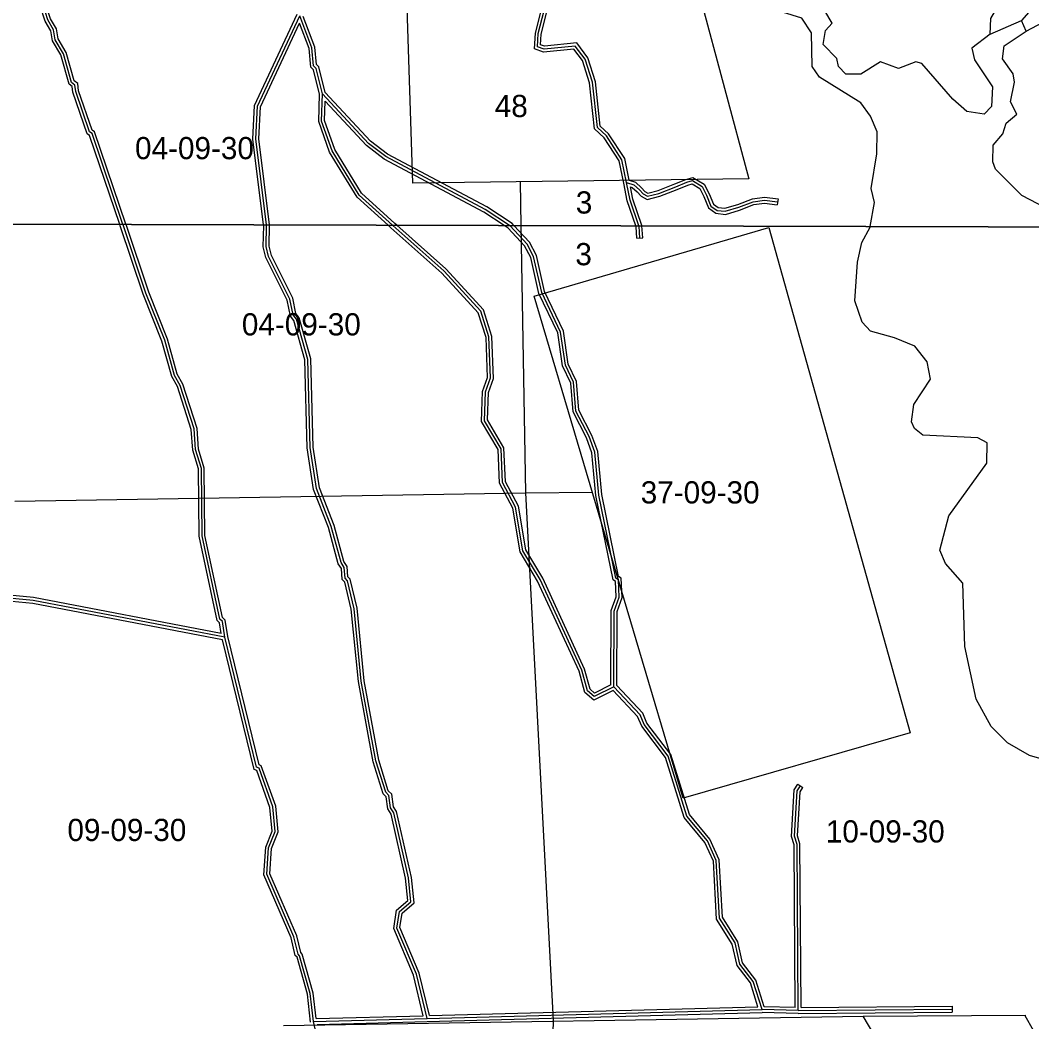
# Model space of a CAD drawing. Extents: x 418523 to 616617, y 1878279 to 2196743.
# Drawn here: x 563379 to 573626, y 1961144 to 1971295 of the extents above; entities that cross this region are included whole.
import ezdxf

# ---------------------------------------------------------------- set-up
doc = ezdxf.new("R2010")
doc.units = 0
for name, color, linetype in [('Level 1', 7, 'Continuous'), ('Level 2', 7, 'Continuous'), ('Level 31', 7, 'Continuous'), ('Level 32', 7, 'Continuous'), ('Level 5', 7, 'Continuous'), ('Level 63', 7, 'Continuous'), ('Level 7', 7, 'Continuous')]:
    doc.layers.add(name, color=color, linetype=linetype)

msp = doc.modelspace()

# ---------------------------------------------------------------- linework, layer by layer
at = {"layer": 'Level 1'}
for p, q in [((567356.046, 1969642.211), (567262.093, 1972599.901)), ((570215.137, 1971717.725), (570759.854, 1969688.182)), ((570759.854, 1969688.182), (567356.046, 1969642.211)), ((568442.603, 1969656.886), (568450.437, 1969213.046)), ((568450.439, 1969213.046), (568498.229, 1966505.171)), ((568584.936, 1968498.066), (570961.931, 1969193.848)), ((570961.931, 1969193.848), (572392.411, 1964072.356)), ((570093.531, 1963410.441), (568584.936, 1968498.066)), ((563325.605, 1966421.114), (568498.229, 1966505.171)), ((568498.229, 1966505.171), (569174.423, 1966510.066)), ((568498.229, 1966505.171), (568776.511, 1961155.102)), ((572392.411, 1964072.356), (570093.531, 1963410.441)), ((566044.955, 1961105.029), (571916.201, 1961201.744)), ((571916.201, 1961201.744), (573565.651, 1961210.564)), ((573305.676, 1958862.184), (571916.201, 1961201.744)), ((573555.637, 1961206.581), (574887.717, 1958874.766)), ((568776.511, 1961155.102), (568644.303, 1955869.218))]:
    msp.add_line(p, q, dxfattribs=at)
at = {"layer": 'Level 31'}
for p, q in [((567499.95, 1961176.461), (570893, 1961267.367)), ((571259.908, 1961257.792), (570893, 1961267.367)), ((571259.908, 1961257.792), (572818.751, 1961270.236)), ((566349.567, 1961146.156), (567499.95, 1961176.461))]:
    msp.add_line(p, q, dxfattribs=at)
for points in [[(569521.172, 1969648.749), (569474.434, 1969880.869), (569316.651, 1970123.071), (569225.138, 1970206.562), (569176.398, 1970665.243), (569101.742, 1970898.885), (569002.099, 1971032.581), (568685.327, 1970999.876), (568618.747, 1971025.127), (568627.315, 1971158.567), (568686.256, 1971391.892), (568753.449, 1971491.737), (568737.065, 1971675.057)], [(564418.857, 1969223.903), (564106.349, 1970145.186), (564081.32, 1970161.976), (563940.811, 1970571.075), (563932.728, 1970637.644), (563899.47, 1970662.819), (563816.744, 1970954.676), (563733.641, 1971096.71), (563717.392, 1971196.756), (563659.254, 1971296.906), (563609.811, 1971447.22), (563601.704, 1971630.521)], [(565874.59, 1969219.983), (565765.254, 1970090.891), (565782.573, 1970424.318), (566210.352, 1971340.039)], [(566441.659, 1970547.438), (566375.649, 1970806.156), (566350.64, 1970831.31), (566334.586, 1971014.63), (566210.352, 1971340.039)], [(567150.249, 1969216.548), (566813.943, 1969521.031), (566540.22, 1969971.899), (566432.422, 1970272.539), (566441.659, 1970547.438)], [(568336.904, 1969213.352), (568088.994, 1969375.771), (567081.772, 1969912.037), (566907.242, 1970045.92), (566441.659, 1970547.438)], [(569521.172, 1969648.749), (569594.74, 1969625.301), (569650.474, 1969575.351), (569688.459, 1969534.532), (569732.198, 1969510.791), (569849.365, 1969539.973), (570021.839, 1969607.572), (570130.155, 1969651.685), (570188.587, 1969669.003), (570285.239, 1969610.23), (570332, 1969522.116), (570375.852, 1969410.737), (570437.314, 1969366.592), (570519.168, 1969357.674), (570656.673, 1969398.811), (570803.096, 1969454.473), (570917.063, 1969472.028), (571051.575, 1969454.261)], [(569646.29, 1969209.826), (569556.616, 1969471.931), (569521.172, 1969648.749)], [(565451.352, 1965041.616), (565426.669, 1965199.866), (565401.657, 1965225.02), (565220.61, 1966067.686), (565214.046, 1966751.005), (565156.126, 1966943.157), (565140.137, 1967151.569), (564999.688, 1967593.756), (564941.542, 1967693.903), (564842.464, 1968052.711), (564651.963, 1968528.478), (564420.431, 1969219.268), (564418.859, 1969223.903)], [(567499.95, 1961176.461), (567392.797, 1961626.921), (567193.956, 1962093.966), (567219.435, 1962260.82), (567336.479, 1962360.542), (567311.987, 1962602.43), (567163.766, 1963261.361), (567130.56, 1963311.261), (567114.357, 1963436.397), (567081.112, 1963469.933), (566981.9, 1963786.914), (566834.053, 1964596.035), (566760.931, 1965329.7), (566694.971, 1965613.509), (566669.959, 1965638.661), (566661.971, 1965747.049), (566628.767, 1965796.951), (566529.688, 1966164.116), (566380.506, 1966547.77), (566315.194, 1966965.039), (566292.3, 1967857.135), (566176.829, 1968265.799), (566143.609, 1968307.7), (566110.673, 1968465.97), (565894.986, 1968899.972), (565870.479, 1969000.037), (565875.133, 1969215.672), (565874.592, 1969219.983)], [(569392.991, 1964539.007), (569192.804, 1964439.476), (569126.292, 1964498.18), (569068.386, 1964706.689), (568645.59, 1965624.823), (568471.412, 1965917.25), (568397.566, 1966359.262), (568264.867, 1966609.408), (568249.18, 1966951.28), (568083.243, 1967235.325), (568092.191, 1967526.953), (568142.673, 1967668.657), (568127.167, 1968085.44), (568044.321, 1968344.195), (567670.196, 1968753.475), (567154.661, 1969212.556), (567150.251, 1969216.548)], [(569392.991, 1964539.007), (569395.116, 1965305.945), (569445.595, 1965447.65), (569437.755, 1965622.585), (569412.721, 1965639.371), (569239.836, 1966481.999), (569199.285, 1966915.567), (569141.264, 1967073.894), (569008.583, 1967332.764), (568984.521, 1967624.834), (568901.471, 1967799.948), (568852.436, 1968133.533), (568661.707, 1968534.368), (568579.433, 1968901.126), (568513.088, 1969026.38), (568342.476, 1969209.704), (568336.906, 1969213.352)], [(569655.359, 1969086.59), (569647.391, 1969206.615), (569646.292, 1969209.826)], [(565451.352, 1965041.616), (563509.914, 1965413.739), (562518.03, 1965507.888), (561585.104, 1965819.014), (560593.401, 1965855.031)], [(566349.567, 1961146.156), (566316.929, 1961429.52), (566209.629, 1961813.435), (566192.847, 1961830.203), (566151.694, 1962005.22), (565878.373, 1962639.371), (565895.531, 1962906.25), (565962.91, 1963072.637), (565938.449, 1963322.89), (565797.852, 1963715.251), (565772.799, 1963723.676), (565451.352, 1965041.616)], [(570893, 1961267.367), (570802.241, 1961550.861), (570669.337, 1961726.45), (570619.69, 1961943.302), (570462.203, 1962193.86), (570430.233, 1962777.231), (570339.289, 1962977.816), (570131.343, 1963228.492), (569941.377, 1963837.326), (569700.588, 1964154.995), (569658.929, 1964255.097), (569392.991, 1964539.007)], [(571259.908, 1961257.792), (571247.601, 1962941.891), (571223.036, 1963025.224), (571249.166, 1963483.729), (571282.607, 1963533.836)], [(566568.709, 1958977.895), (566419.856, 1959378.637), (566437.612, 1959761.882), (566471.368, 1959937.081), (566456.648, 1960670.601), (566349.567, 1961146.156)]]:
    msp.add_lwpolyline(points, dxfattribs=at)
at = {"layer": 'Level 32'}
for p, q in [((571055.504, 1969484.004), (571047.647, 1969424.519)), ((569685.294, 1969088.577), (569677.25, 1969209.742)), ((569625.424, 1969084.603), (569685.294, 1969088.577)), ((571257.654, 1963550.49), (571307.561, 1963517.181)), ((567523.501, 1961207.104), (570852.242, 1961296.286)), ((571229.681, 1961288.591), (570915.078, 1961296.801)), ((571289.69, 1961288.031), (572818.513, 1961300.235)), ((572818.513, 1961300.235), (572818.991, 1961240.236)), ((566376.23, 1961176.868), (567462.211, 1961205.478)), ((567500.754, 1961146.471), (570893.011, 1961237.355)), ((571259.637, 1961227.787), (570893.011, 1961237.356)), ((571259.636, 1961227.788), (572818.991, 1961240.236)), ((566386.856, 1961117.126), (567500.741, 1961146.471))]:
    msp.add_line(p, q, dxfattribs=at)
for points in [[(564387.149, 1969223.989), (564081.201, 1970125.931), (564056.225, 1970142.686), (563911.411, 1970564.32), (563904.479, 1970621.401), (563873.349, 1970644.966), (563788.921, 1970942.821), (563704.925, 1971086.383), (563688.666, 1971186.481), (563631.734, 1971284.556), (563580.022, 1971441.768), (563573.461, 1971590.122)], [(564450.545, 1969223.818), (564448.858, 1969228.854), (564131.497, 1970164.442), (564106.415, 1970181.267), (563970.212, 1970577.83), (563960.976, 1970653.887), (563925.593, 1970680.671), (563844.565, 1970966.531), (563762.358, 1971107.036), (563746.117, 1971207.029), (563686.774, 1971309.256), (563639.6, 1971452.671), (563633.47, 1971591.27)], [(569491.761, 1969642.826), (569446.158, 1969869.311), (569293.604, 1970103.488), (569196.509, 1970192.072), (569146.889, 1970659.028), (569074.691, 1970884.978), (568988.229, 1971000.988), (568681.335, 1970969.304), (568587.389, 1971004.935), (568597.553, 1971163.241), (568658.449, 1971404.306), (568722.62, 1971499.662), (568710.539, 1971634.848)], [(569547.099, 1969671.972), (569502.709, 1969892.427), (569339.699, 1970142.652), (569253.768, 1970221.052), (569205.907, 1970671.458), (569128.793, 1970912.792), (569015.969, 1971064.173), (568689.318, 1971030.449), (568650.106, 1971045.32), (568657.078, 1971153.892), (568714.064, 1971379.478), (568784.277, 1971483.812), (568770.348, 1971639.691)], [(565844.343, 1969220.064), (565735.155, 1970089.792), (565752.916, 1970431.716), (566185.139, 1971356.949)], [(565904.837, 1969219.901), (565795.352, 1970091.99), (565812.229, 1970416.92), (566207.574, 1971263.206)], [(566411.532, 1970544.167), (566348.603, 1970790.809), (566321.703, 1970817.865), (566305.064, 1971007.841), (566207.574, 1971263.206)], [(566468.84, 1970562.253), (566402.695, 1970821.504), (566379.579, 1970844.755), (566364.108, 1971021.418), (566245.009, 1971333.375)], [(567105.418, 1969216.669), (566790.566, 1969501.726), (566513.004, 1969958.921), (566402.245, 1970267.813), (566411.532, 1970544.167)], [(568380.169, 1969213.236), (568361.957, 1969232.806), (568104.295, 1969401.611), (567098.062, 1969937.352), (566927.508, 1970068.184), (566468.84, 1970562.252)], [(567195.424, 1969216.426), (567174.702, 1969234.878), (566837.319, 1969540.337), (566567.438, 1969984.877), (566462.598, 1970277.265), (566469.199, 1970473.677)], [(568281.934, 1969213.501), (568073.693, 1969349.93), (567065.482, 1969886.722), (566886.976, 1970023.656), (566469.199, 1970473.677)], [(569547.099, 1969671.972), (569609.975, 1969651.933), (569671.51, 1969596.784), (569707.081, 1969558.56), (569736.261, 1969542.721), (569840.228, 1969568.615), (570010.707, 1969635.431), (570120.21, 1969680.027), (570192.811, 1969701.546), (570307.873, 1969631.578), (570359.294, 1969534.684), (570400.529, 1969429.95), (570448.407, 1969395.562), (570516.384, 1969388.156), (570647.03, 1969427.241), (570795.397, 1969483.642), (570916.736, 1969502.332), (571055.504, 1969484.004)], [(569614.553, 1969209.911), (569527.589, 1969464.092), (569491.756, 1969642.852)], [(569677.248, 1969209.742), (569677.06, 1969212.566), (569585.642, 1969479.768), (569560.6, 1969604.694)], [(569560.601, 1969604.694), (569579.504, 1969598.67), (569629.439, 1969553.917), (569669.838, 1969510.505), (569728.134, 1969478.862), (569858.503, 1969511.331), (570032.972, 1969579.712), (570140.1, 1969623.341), (570184.362, 1969636.46), (570262.604, 1969588.881), (570304.705, 1969509.55), (570351.174, 1969391.525), (570426.221, 1969337.622), (570521.952, 1969327.192), (570666.315, 1969370.381), (570810.795, 1969425.305), (570917.389, 1969441.725), (571047.647, 1969424.519)], [(565415.142, 1965079.103), (565398.527, 1965185.62), (565374.176, 1965210.11), (565190.64, 1966064.356), (565184.088, 1966746.441), (565126.461, 1966937.616), (565110.491, 1967145.805), (564972.091, 1967581.537), (564913.654, 1967682.187), (564813.991, 1968043.112), (564623.792, 1968518.127), (564392.003, 1969209.683), (564387.151, 1969223.989)], [(565480.8, 1965047.491), (565454.81, 1965214.112), (565429.14, 1965239.93), (565250.58, 1966071.014), (565244.004, 1966755.569), (565185.789, 1966948.698), (565169.783, 1967157.334), (565027.286, 1967605.973), (564969.43, 1967705.62), (564870.937, 1968062.309), (564680.135, 1968538.83), (564450.547, 1969223.818)], [(567462.211, 1961205.478), (567364.199, 1961617.506), (567163.011, 1962090.061), (567191.465, 1962276.403), (567305.046, 1962373.174), (567282.322, 1962597.609), (567135.715, 1963249.362), (567101.706, 1963300.468), (567085.907, 1963422.482), (567054.663, 1963454), (566952.719, 1963779.711), (566804.321, 1964591.844), (566731.271, 1965324.796), (566667.68, 1965598.406), (566640.856, 1965625.381), (566632.63, 1965736.988), (566601.078, 1965784.407), (566501.143, 1966154.745), (566351.369, 1966539.923), (566285.254, 1966962.323), (566262.406, 1967852.601), (566149.591, 1968251.865), (566115.685, 1968294.631), (566082.089, 1968456.077), (565866.639, 1968889.601), (565840.4, 1968996.736), (565845.091, 1969214.119), (565844.345, 1969220.064)], [(567523.5, 1961207.104), (567421.396, 1961636.334), (567224.901, 1962097.869), (567247.404, 1962245.236), (567367.912, 1962347.91), (567341.653, 1962607.251), (567191.817, 1963273.36), (567159.413, 1963322.055), (567142.807, 1963450.311), (567107.561, 1963485.866), (567011.081, 1963794.118), (566863.785, 1964600.226), (566790.591, 1965334.603), (566722.261, 1965628.612), (566699.061, 1965651.941), (566691.311, 1965757.11), (566656.456, 1965809.494), (566558.233, 1966173.487), (566409.645, 1966555.616), (566345.135, 1966967.755), (566322.194, 1967861.669), (566204.066, 1968279.733), (566171.533, 1968320.769), (566139.258, 1968475.863), (565923.334, 1968910.343), (565900.557, 1969003.338), (565905.175, 1969217.225), (565904.839, 1969219.901)], [(569386.359, 1964502.204), (569188.086, 1964403.626), (569099.766, 1964481.576), (569040.126, 1964696.334), (568619.003, 1965610.834), (568442.751, 1965906.743), (568368.778, 1966349.511), (568235.206, 1966601.302), (568219.549, 1966942.525), (568052.992, 1967227.632), (568062.349, 1967532.582), (568112.479, 1967673.298), (568097.34, 1968080.212), (568017.751, 1968328.797), (567649.092, 1968732.096), (567134.617, 1969190.233), (567105.42, 1969216.669)], [(569363.043, 1964557.62), (569197.523, 1964475.326), (569152.817, 1964514.783), (569096.646, 1964717.044), (568672.177, 1965638.811), (568500.074, 1965927.756), (568426.353, 1966369.015), (568294.528, 1966617.515), (568278.811, 1966960.035), (568113.493, 1967243.018), (568122.034, 1967521.323), (568172.867, 1967664.016), (568156.995, 1968090.668), (568070.893, 1968359.592), (567691.298, 1968774.854), (567195.426, 1969216.426)], [(569363.043, 1964557.621), (569365.129, 1965311.168), (569415.361, 1965452.18), (569408.462, 1965606.106), (569385.803, 1965621.301), (569210.117, 1966477.574), (569169.776, 1966908.899), (569113.727, 1967061.846), (568979.172, 1967324.373), (568955.07, 1967616.92), (568872.441, 1967791.146), (568823.41, 1968124.712), (568633.171, 1968524.517), (568551.041, 1968890.636), (568488.43, 1969008.839), (568322.992, 1969186.602), (568281.936, 1969213.501)], [(569423.026, 1964550.827), (569425.102, 1965300.721), (569475.829, 1965443.121), (569467.046, 1965639.064), (569439.639, 1965657.442), (569269.554, 1966486.423), (569228.793, 1966922.236), (569168.8, 1967085.942), (569037.995, 1967341.155), (569013.971, 1967632.748), (568930.499, 1967808.75), (568881.462, 1968142.355), (568690.243, 1968544.218), (568607.826, 1968911.615), (568537.747, 1969043.921), (568380.171, 1969213.236)], [(569625.424, 1969084.603), (569617.719, 1969200.662), (569614.555, 1969209.911)], [(565426.775, 1965015.779), (563505.664, 1965384.006), (562511.786, 1965478.345), (561579.704, 1965789.19), (560596.259, 1965824.905)], [(565415.142, 1965079.103), (563514.165, 1965443.471), (562524.272, 1965537.431), (561590.503, 1965848.838), (560627.195, 1965883.823)], [(566319.948, 1961141.129), (566287.396, 1961423.73), (566182.854, 1961797.777), (566165.598, 1961815.02), (566123.096, 1961995.776), (565847.973, 1962634.109), (565865.904, 1962913.015), (565932.335, 1963077.06), (565908.952, 1963316.271), (565774.513, 1963691.448), (565747.57, 1963700.509), (565426.775, 1965015.78)], [(566376.229, 1961176.868), (566346.461, 1961435.309), (566236.403, 1961829.092), (566220.096, 1961845.386), (566180.291, 1962014.664), (565908.774, 1962644.632), (565925.159, 1962899.485), (565993.486, 1963068.214), (565967.945, 1963329.51), (565821.191, 1963739.055), (565798.029, 1963746.844), (565480.8, 1965047.491)], [(570852.241, 1961296.286), (570775.231, 1961536.838), (570641.53, 1961713.478), (570591.581, 1961931.646), (570432.672, 1962184.466), (570400.585, 1962769.97), (570313.627, 1962961.76), (570104.469, 1963213.899), (569914.301, 1963823.384), (569674.364, 1964139.928), (569633.318, 1964238.554), (569386.359, 1964502.204)], [(570915.078, 1961296.801), (570829.253, 1961564.885), (570697.144, 1961739.421), (570647.797, 1961954.958), (570491.734, 1962203.253), (570459.881, 1962784.494), (570364.95, 1962993.871), (570158.216, 1963243.086), (569968.455, 1963851.268), (569726.813, 1964170.061), (569684.539, 1964271.641), (569423.026, 1964550.828)], [(571229.681, 1961288.591), (571217.631, 1962937.453), (571192.787, 1963021.734), (571219.678, 1963493.589), (571257.654, 1963550.49)], [(571289.69, 1961288.031), (571277.57, 1962946.328), (571253.284, 1963028.714), (571278.653, 1963473.868), (571307.561, 1963517.181)]]:
    msp.add_lwpolyline(points, dxfattribs=at)
at = {"layer": 'Level 5'}
msp.add_line((573203.562, 1971152.431), (573520.797, 1971293.139), dxfattribs=at)
for points in [[(573203.562, 1971152.431), (573019.699, 1971011.336), (573044.323, 1970894.534), (573226.832, 1970618.84), (573217.845, 1970418.806), (573142.594, 1970344.002), (572967.63, 1970369.601), (572826.294, 1970495.101), (572510.66, 1970854.586), (572452.369, 1970871.456), (572277.075, 1970805.321), (572093.91, 1970872.601), (571893.448, 1970748.205), (571743.384, 1970748.693), (571668.591, 1970823.954), (571652.179, 1970907.376), (571510.913, 1971049.556), (571536.411, 1971191.171), (571603.331, 1971266.003), (571454.093, 1971516.586), (571463.149, 1971741.631), (571638.701, 1971891.097), (571622.588, 1972066.231), (571365.534, 1972492.237)], [(573203.562, 1971152.431), (573212.419, 1971310.826), (573430.398, 1971693.577), (573522.458, 1971809.991), (573522.756, 1971901.693), (573373.289, 1972077.245), (573440.568, 1972260.42), (573432.555, 1972360.492), (573382.763, 1972435.683)], [(573570.45, 1971184.607), (573804.294, 1971308.903), (573788.478, 1971575.729), (573755.286, 1971625.84), (573680.364, 1971659.42), (573588.563, 1971626.368), (573546.653, 1971559.836), (573596.087, 1971376.272), (573520.797, 1971293.139)], [(574280.983, 1969198.232), (574289.74, 1969331.585), (574240.117, 1969456.787), (574181.924, 1969507.007), (573881.36, 1969366.271), (573764.747, 1969391.639), (573523.389, 1969517.469), (573257.508, 1969785.111), (573232.725, 1969860.203), (573233.283, 1970026.926), (573333.673, 1970143.311), (573367.382, 1970251.583), (573476.043, 1970342.927), (573409.749, 1970468.199), (573452.076, 1970668.144), (573435.674, 1970751.536), (573327.789, 1970901.958), (573344.887, 1971035.271), (573570.45, 1971184.607)]]:
    msp.add_lwpolyline(points, dxfattribs=at)
at = {"layer": 'Level 63'}
for points in [[(537233.895, 1969297.112), (576901.845, 1969190.287), (576999.639, 2014646.963), (537381.014, 2014754.121), (537233.895, 1969297.112)], [(537087.28, 1923840.983), (576804.214, 1923734.416), (576901.847, 1969190.287), (537233.897, 1969297.112), (537087.28, 1923840.983)]]:
    msp.add_lwpolyline(points, dxfattribs=at)
at = {"layer": 'Level 7'}
for p, q in [((573570.45, 1971184.607), (573520.797, 1971293.139)), ((571988.46, 1969197.311), (571989.515, 1969203.516))]:
    msp.add_line(p, q, dxfattribs=at)
for points in [[(571989.513, 1969203.516), (572030.954, 1969447.277), (571998.061, 1969589.09), (572057.556, 1969939.059), (572058.282, 1970164.104), (571992.108, 1970322.726), (571892.493, 1970456.428), (571476.498, 1970716.199), (571401.824, 1970824.83), (571394.598, 1971166.628), (571295.053, 1971317), (570653.804, 1971519.166), (570354.641, 1971820.229), (570330.486, 1972078.754), (570397.536, 1972186.898), (570873.722, 1972502.141), (572762.202, 1973879.898), (573037.796, 1974029.035)], [(573837.296, 1963776.347), (573604.11, 1963843.786), (573379.413, 1963969.556), (573213.216, 1964136.837), (573064.04, 1964412.391), (572949.06, 1964946.313), (572926.111, 1965588.278), (572751.674, 1965788.901), (572693.741, 1965922.482), (572786.588, 1966272.312), (573171.76, 1966804.6), (573172.447, 1967013.005), (573080.905, 1967063.325), (572522.441, 1967090.128), (572439.298, 1967157.078), (572406.156, 1967223.9), (572431.715, 1967398.864), (572599.295, 1967656.772), (572566.501, 1967831.936), (572441.986, 1967990.718), (572233.831, 1968074.767), (571992.274, 1968142.206), (571909.211, 1968234.207), (571834.896, 1968451.181), (571861.151, 1968842.891), (571903.49, 1969042.826), (571988.46, 1969197.311)]]:
    msp.add_lwpolyline(points, dxfattribs=at)

# ---------------------------------------------------------------- texts
at = {"layer": 'Level 2'}
for s, p in [('48', (568185.897, 1970312.987)), ('04-09-30', (564541.965, 1969885.857)), ('3', (569006.67, 1969335.051)), ('3', (569002.219, 1968811.136)), ('04-09-30', (565624.25, 1968099.873)), ('37-09-30', (569664.289, 1966396.77)), ('09-09-30', (563857.026, 1962975.543)), ('10-09-30', (571539.387, 1962960.529))]:
    msp.add_text(s, height=225, dxfattribs=at).set_placement(p)

doc.saveas('drawing.dxf')
